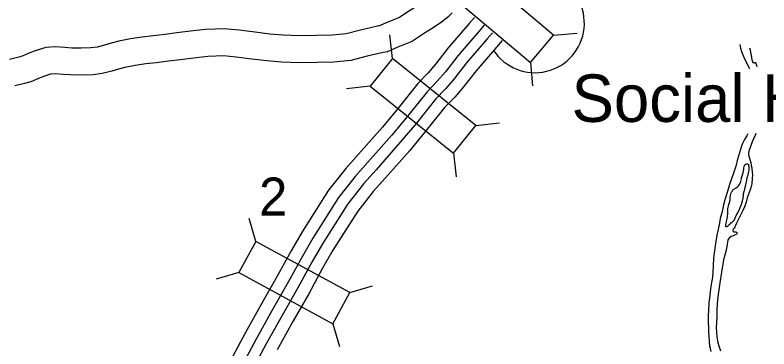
# Model space of a CAD drawing. Extents: x 1373862 to 1377080, y 1164775 to 1170415.
# Drawn here: x 1374478.2 to 1374562, y 1170199.4 to 1170236.6 of the extents above; entities that cross this region are included whole.
import ezdxf

# ---------------------------------------------------------------- set-up
doc = ezdxf.new("R2010")
doc.units = 0
doc.layers.add('Default', color=7, linetype='Continuous')

msp = doc.modelspace()

# ---------------------------------------------------------------- linework, layer by layer
at = {"layer": 'Default'}
for p, q in [((1374520.172, 1170231.751), (1374519.885, 1170234.375)), ((1374538.06, 1170234.352), (1374540.69, 1170234.574)), ((1374535.505, 1170231.326), (1374535.727, 1170228.696)), ((1374517.694, 1170228.662), (1374515.069, 1170228.375)), ((1374529.437, 1170224.315), (1374532.062, 1170224.602)), ((1374526.959, 1170221.226), (1374527.246, 1170218.602)), ((1374505.003, 1170211.413), (1374504.259, 1170213.946)), ((1374503.104, 1170207.938), (1374500.571, 1170207.194)), ((1374515.429, 1170205.718), (1374517.962, 1170206.462)), ((1374513.53, 1170202.243), (1374514.274, 1170199.71))]:
    msp.add_line(p, q, dxfattribs=at)
for points in [[(1374538.06, 1170234.352), (1374528.983, 1170242.017), (1374526.428, 1170238.991), (1374535.505, 1170231.326)], [(1374517.694, 1170228.662), (1374526.959, 1170221.226), (1374529.437, 1170224.315), (1374520.172, 1170231.751)], [(1374515.429, 1170205.718), (1374505.003, 1170211.413), (1374503.104, 1170207.938), (1374513.53, 1170202.243)]]:
    msp.add_lwpolyline(points, close=True, dxfattribs=at)
for points in [[(1374518.677, 1170235.385), (1374519.448, 1170235.728), (1374520.876, 1170236.299), (1374522.076, 1170237.111), (1374523.056, 1170237.738), (1374523.89, 1170238.282), (1374524.465, 1170238.729), (1374524.788, 1170239.053)], [(1374529.302, 1170236.323), (1374528.719, 1170235.655), (1374526.366, 1170232.926), (1374524.995, 1170231.155), (1374524.134, 1170230.164), (1374522.988, 1170228.964), (1374520.801, 1170226.239), (1374519.049, 1170224.134), (1374516.413, 1170221.125), (1374514.983, 1170219.531), (1374513.062, 1170217.093), (1374510.135, 1170212.488), (1374508.921, 1170210.367), (1374507.375, 1170207.537), (1374505.618, 1170204.445), (1374503.846, 1170201.266), (1374502.131, 1170198.091)], [(1374519.577, 1170232.502), (1374520.616, 1170232.964), (1374522.289, 1170233.633), (1374523.725, 1170234.605), (1374524.684, 1170235.218), (1374525.633, 1170235.837), (1374526.454, 1170236.476), (1374526.828, 1170236.85)], [(1374518.677, 1170235.385), (1374518.513, 1170235.354), (1374516.632, 1170234.917), (1374515.035, 1170234.506), (1374513.484, 1170234.357), (1374511.715, 1170234.303), (1374509.796, 1170234.267), (1374508.014, 1170234.348), (1374506.534, 1170234.47), (1374504.915, 1170234.673), (1374503.129, 1170234.891), (1374501.481, 1170235.038), (1374499.438, 1170234.988), (1374498.032, 1170234.818), (1374496.203, 1170234.602), (1374494.911, 1170234.44), (1374493.559, 1170234.268), (1374492.363, 1170234.126), (1374491.065, 1170233.927), (1374489.774, 1170233.682), (1374488.896, 1170233.454), (1374488.165, 1170233.229), (1374487.344, 1170233.022), (1374486.639, 1170232.934), (1374485.565, 1170232.889), (1374484.519, 1170232.916), (1374483.762, 1170232.978), (1374482.729, 1170233.036), (1374481.64, 1170232.974), (1374480.472, 1170232.623), (1374479.686, 1170232.298), (1374478.997, 1170232.013), (1374478.508, 1170231.871), (1374477.605, 1170231.662)], [(1374530.377, 1170235.464), (1374529.757, 1170234.754), (1374527.431, 1170232.056), (1374526.059, 1170230.283), (1374525.15, 1170229.238), (1374524.023, 1170228.057), (1374521.865, 1170225.369), (1374520.094, 1170223.241), (1374517.441, 1170220.212), (1374516.036, 1170218.646), (1374514.185, 1170216.297), (1374511.312, 1170211.777), (1374510.121, 1170209.696), (1374508.576, 1170206.868), (1374506.816, 1170203.771), (1374505.051, 1170200.605), (1374503.339, 1170197.434)], [(1374531.303, 1170234.623), (1374530.702, 1170233.934), (1374528.399, 1170231.265), (1374527.025, 1170229.489), (1374526.074, 1170228.395), (1374524.964, 1170227.233), (1374522.833, 1170224.578), (1374521.045, 1170222.429), (1374518.377, 1170219.383), (1374516.993, 1170217.841), (1374515.207, 1170215.573), (1374512.383, 1170211.131), (1374511.212, 1170209.086), (1374509.668, 1170206.259), (1374507.905, 1170203.157), (1374506.147, 1170200.004), (1374504.437, 1170196.836)], [(1374532.377, 1170233.764), (1374531.74, 1170233.033), (1374529.464, 1170230.394), (1374528.089, 1170228.617), (1374527.091, 1170227.469), (1374526, 1170226.326), (1374523.898, 1170223.707), (1374522.091, 1170221.536), (1374519.405, 1170218.471), (1374518.046, 1170216.956), (1374516.33, 1170214.777), (1374513.56, 1170210.42), (1374512.412, 1170208.414), (1374510.869, 1170205.59), (1374509.103, 1170202.483), (1374507.353, 1170199.342)], [(1374558.805, 1170233.307), (1374558.865, 1170232.887), (1374558.977, 1170232.547), (1374559.13, 1170232.148), (1374559.314, 1170231.719), (1374559.557, 1170231.23), (1374559.791, 1170230.742), (1374559.859, 1170230.595)], [(1374559.849, 1170232.93), (1374559.945, 1170232.686), (1374560.06, 1170232.056), (1374560.071, 1170231.936), (1374560.092, 1170231.796), (1374560.123, 1170231.646), (1374560.164, 1170231.526), (1374560.205, 1170231.416), (1374560.245, 1170231.326), (1374560.285, 1170231.297), (1374560.345, 1170231.277), (1374560.405, 1170231.268), (1374560.465, 1170231.298), (1374560.525, 1170231.299), (1374560.555, 1170231.259), (1374560.607, 1170231.089), (1374560.665, 1170230.874)], [(1374519.577, 1170232.502), (1374519.131, 1170232.418), (1374517.345, 1170232.002), (1374515.555, 1170231.542), (1374513.674, 1170231.362), (1374511.789, 1170231.304), (1374509.756, 1170231.266), (1374507.822, 1170231.354), (1374506.225, 1170231.486), (1374504.546, 1170231.696), (1374502.814, 1170231.908), (1374501.385, 1170232.035), (1374499.655, 1170231.993), (1374498.388, 1170231.839), (1374496.566, 1170231.624), (1374495.286, 1170231.463), (1374493.925, 1170231.291), (1374492.767, 1170231.153), (1374491.572, 1170230.97), (1374490.431, 1170230.753), (1374489.715, 1170230.567), (1374488.972, 1170230.339), (1374487.899, 1170230.069), (1374486.889, 1170229.942), (1374485.588, 1170229.887), (1374484.357, 1170229.92), (1374483.556, 1170229.985), (1374482.731, 1170230.031), (1374482.164, 1170229.999), (1374481.48, 1170229.793), (1374480.833, 1170229.526), (1374479.989, 1170229.177), (1374479.263, 1170228.967), (1374478.193, 1170228.719)], [(1374559.68, 1170223.385), (1374559.564, 1170223.139), (1374559.317, 1170222.736), (1374559.091, 1170222.314), (1374558.993, 1170222.112), (1374558.838, 1170221.53), (1374558.488, 1170220.426), (1374558.372, 1170219.884), (1374558.08, 1170219), (1374557.651, 1170217.745), (1374557.476, 1170217.202), (1374557.184, 1170216.238), (1374557.009, 1170215.676), (1374556.807, 1170214.733), (1374556.614, 1170213.95), (1374556.528, 1170213.459), (1374556.364, 1170212.746), (1374556.24, 1170212.114), (1374556.126, 1170211.412), (1374556.06, 1170210.911), (1374555.947, 1170210.089), (1374555.872, 1170209.508), (1374555.828, 1170208.716), (1374555.784, 1170207.975), (1374555.749, 1170207.444), (1374555.692, 1170207.032), (1374555.577, 1170206.421), (1374555.493, 1170205.769), (1374555.399, 1170205.087), (1374555.343, 1170204.566), (1374555.3, 1170203.784), (1374555.266, 1170203.053), (1374555.271, 1170202.432), (1374555.306, 1170201.792), (1374555.32, 1170201.311), (1374555.333, 1170200.911), (1374555.368, 1170200.29), (1374555.432, 1170199.79), (1374555.484, 1170199.53), (1374555.474, 1170199.51), (1374555.577, 1170199.16)], [(1374560.57, 1170223.418), (1374560.521, 1170223.307), (1374560.354, 1170222.895), (1374560.158, 1170222.483), (1374560.002, 1170222.061), (1374559.924, 1170221.86), (1374559.865, 1170221.679), (1374559.807, 1170221.458), (1374559.769, 1170221.198), (1374559.77, 1170221.088), (1374559.792, 1170220.898), (1374559.864, 1170220.658), (1374559.955, 1170220.398), (1374559.997, 1170220.198), (1374560.06, 1170219.848), (1374560.112, 1170219.598), (1374560.133, 1170219.468), (1374560.165, 1170219.138), (1374560.178, 1170218.808), (1374560.171, 1170218.447), (1374560.117, 1170217.796), (1374560, 1170217.364), (1374559.825, 1170216.852), (1374559.62, 1170216.249), (1374559.474, 1170215.777), (1374559.289, 1170215.245), (1374559.103, 1170214.783), (1374558.946, 1170214.461), (1374558.799, 1170214.169), (1374558.641, 1170213.878), (1374558.415, 1170213.455), (1374558.297, 1170213.194), (1374558.239, 1170213.003), (1374558.17, 1170212.872), (1374558.131, 1170212.832), (1374558.041, 1170212.761), (1374558.032, 1170212.731), (1374558.012, 1170212.66), (1374558.013, 1170212.6), (1374558.033, 1170212.54), (1374558.053, 1170212.501), (1374558.114, 1170212.471), (1374558.153, 1170212.481), (1374558.223, 1170212.472), (1374558.303, 1170212.473), (1374558.353, 1170212.473), (1374558.423, 1170212.454)], [(1374558.983, 1170218.467), (1374559.139, 1170218.919), (1374559.158, 1170219.049), (1374559.186, 1170219.28), (1374559.215, 1170219.41), (1374559.243, 1170219.601), (1374559.272, 1170219.751), (1374559.291, 1170219.832), (1374559.36, 1170219.942), (1374559.43, 1170219.983), (1374559.499, 1170220.014), (1374559.609, 1170220.035), (1374559.659, 1170220.035), (1374559.709, 1170220.006), (1374559.74, 1170219.946), (1374559.76, 1170219.896), (1374559.77, 1170219.836), (1374559.791, 1170219.756), (1374559.792, 1170219.686), (1374559.802, 1170219.586), (1374559.793, 1170219.465), (1374559.774, 1170219.345), (1374559.717, 1170219.054), (1374559.669, 1170218.773), (1374559.582, 1170218.492), (1374559.524, 1170218.171), (1374559.457, 1170217.87), (1374559.37, 1170217.529), (1374559.303, 1170217.238), (1374559.215, 1170216.917), (1374559.167, 1170216.716), (1374559.149, 1170216.486), (1374559.121, 1170216.225), (1374559.064, 1170215.894), (1374558.986, 1170215.643), (1374558.898, 1170215.412), (1374558.791, 1170215.131), (1374558.673, 1170214.859), (1374558.506, 1170214.557), (1374558.3, 1170214.135), (1374558.241, 1170213.994), (1374558.143, 1170213.753), (1374558.074, 1170213.682), (1374558.054, 1170213.652), (1374557.985, 1170213.572), (1374557.895, 1170213.511), (1374557.806, 1170213.46), (1374557.697, 1170213.369), (1374557.548, 1170213.227), (1374557.529, 1170213.197), (1374557.479, 1170213.127), (1374557.42, 1170213.076), (1374557.39, 1170213.056), (1374557.35, 1170213.045), (1374557.3, 1170213.025), (1374557.25, 1170213.075), (1374557.23, 1170213.114), (1374557.229, 1170213.174), (1374557.238, 1170213.285), (1374557.257, 1170213.405), (1374557.316, 1170213.616), (1374557.373, 1170213.947), (1374557.411, 1170214.167), (1374557.438, 1170214.478), (1374557.447, 1170214.578), (1374557.465, 1170214.859), (1374557.464, 1170215.039), (1374557.482, 1170215.21), (1374557.511, 1170215.37), (1374557.549, 1170215.521), (1374557.667, 1170215.842)], [(1374557.667, 1170215.842), (1374557.715, 1170216.033), (1374557.723, 1170216.303), (1374557.751, 1170216.524), (1374557.77, 1170216.664), (1374557.828, 1170216.815), (1374557.917, 1170216.976), (1374557.956, 1170217.046), (1374558.006, 1170217.097), (1374558.065, 1170217.167), (1374558.184, 1170217.259), (1374558.234, 1170217.289), (1374558.363, 1170217.36), (1374558.413, 1170217.391), (1374558.532, 1170217.472), (1374558.581, 1170217.522), (1374558.651, 1170217.603), (1374558.759, 1170217.754), (1374558.828, 1170217.895), (1374558.906, 1170218.086), (1374558.964, 1170218.367), (1374558.983, 1170218.467)], [(1374558.423, 1170212.454), (1374558.463, 1170212.444), (1374558.464, 1170212.374), (1374558.454, 1170212.304), (1374558.415, 1170212.223), (1374558.366, 1170212.163), (1374558.207, 1170212.101), (1374558.067, 1170212.03), (1374557.948, 1170211.989), (1374557.818, 1170211.948), (1374557.61, 1170211.786), (1374557.452, 1170211.574), (1374557.338, 1170210.842), (1374557.223, 1170210.3), (1374556.991, 1170209.357), (1374556.743, 1170208.003), (1374556.553, 1170206.81), (1374556.421, 1170205.777), (1374556.356, 1170205.246), (1374556.282, 1170204.464), (1374556.248, 1170203.753), (1374556.234, 1170203.101), (1374556.18, 1170202.38), (1374556.174, 1170201.839), (1374556.178, 1170201.338), (1374556.243, 1170200.758), (1374556.338, 1170200.168), (1374556.441, 1170199.788), (1374556.625, 1170199.229)]]:
    msp.add_lwpolyline(points, dxfattribs=at)
msp.add_arc((1374536.009, 1170235.678), 5.5, 213.32986, 64.30591, dxfattribs=at)

# ---------------------------------------------------------------- texts
for s, height, p in [('Social Hill', 5.27999, (1374540.081, 1170224.7)), ('2', 4.224, (1374505.348, 1170214.284))]:
    msp.add_text(s, height=height, dxfattribs=at).set_placement(p)

doc.saveas('drawing.dxf')
